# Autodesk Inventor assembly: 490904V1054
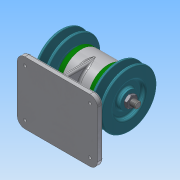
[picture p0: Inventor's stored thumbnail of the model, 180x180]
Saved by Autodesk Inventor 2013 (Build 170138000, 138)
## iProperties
Created: 2019-09
Part Number: 490904V1054
Document SubType Name: Assembly
Designer: Administrator
Author: Administrator
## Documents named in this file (10)
- C:\Users\Administrator\Desktop\490904V1054\답안조립품.iam
- C:\Users\Administrator\Desktop\490904V1054\본체.ipt
- C:\Users\Administrator\Desktop\490904V1054\V-벨트풀리.ipt
- C:\Users\Administrator\Desktop\490904V1054\너트 M10x1.ipt
- C:\Users\Administrator\Desktop\490904V1054\베어링 6004.ipt
- C:\Users\Administrator\Desktop\490904V1054\볼트 M4.ipt
- C:\Users\Administrator\Desktop\490904V1054\오일 실 17 30 5.ipt
- C:\Users\Administrator\Desktop\490904V1054\축.ipt
- C:\Users\Administrator\Desktop\490904V1054\커버.ipt
- C:\Users\Administrator\Desktop\490904V1054\키 5 x 5 x 12.ipt
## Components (2 placed, 1 different names)
1. V-벨트풀리:1
2. V-벨트풀리:2
